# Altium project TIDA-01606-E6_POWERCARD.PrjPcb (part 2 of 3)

## Sheet TIDA-01606-E6_POWERCARD_Power Stage_Pg2.SchDoc
size 431 x 279 mm; Date: Not shown in title block; ApprovedBy: Not shown in title block; CheckedBy: Not shown in title block; Author: Not shown in title block; CompanyName: Not shown in title block; DrawnBy: Murali P; Engineer: Not shown in title block; Organization: Not shown in title block; Address1: Not shown in title block; Address2: Not shown in title block; Address3: Not shown in title block; Address4: Not shown in title block; DocumentNumber: 1; Revision: Use project parameter SCH_Rev; SheetNumber: 2; SheetTotal: 7; PageSetup: Record=PageOptions¦CenterHorizontal=True¦CenterVertical=True¦PrintScale=1.00¦XCorrection=1.00¦YCorrection=1.00¦PrintKind=0¦BorderSize=5000000¦LeftOffset=0¦BottomOffset=0¦Orientation=2¦PaperLength=1000¦PaperWidth=1000¦Scale=100¦PaperSource=15¦PrintQuality=600¦MediaType=1¦DitherType=10¦PaperKind=Letter¦PrintScaleMode=1
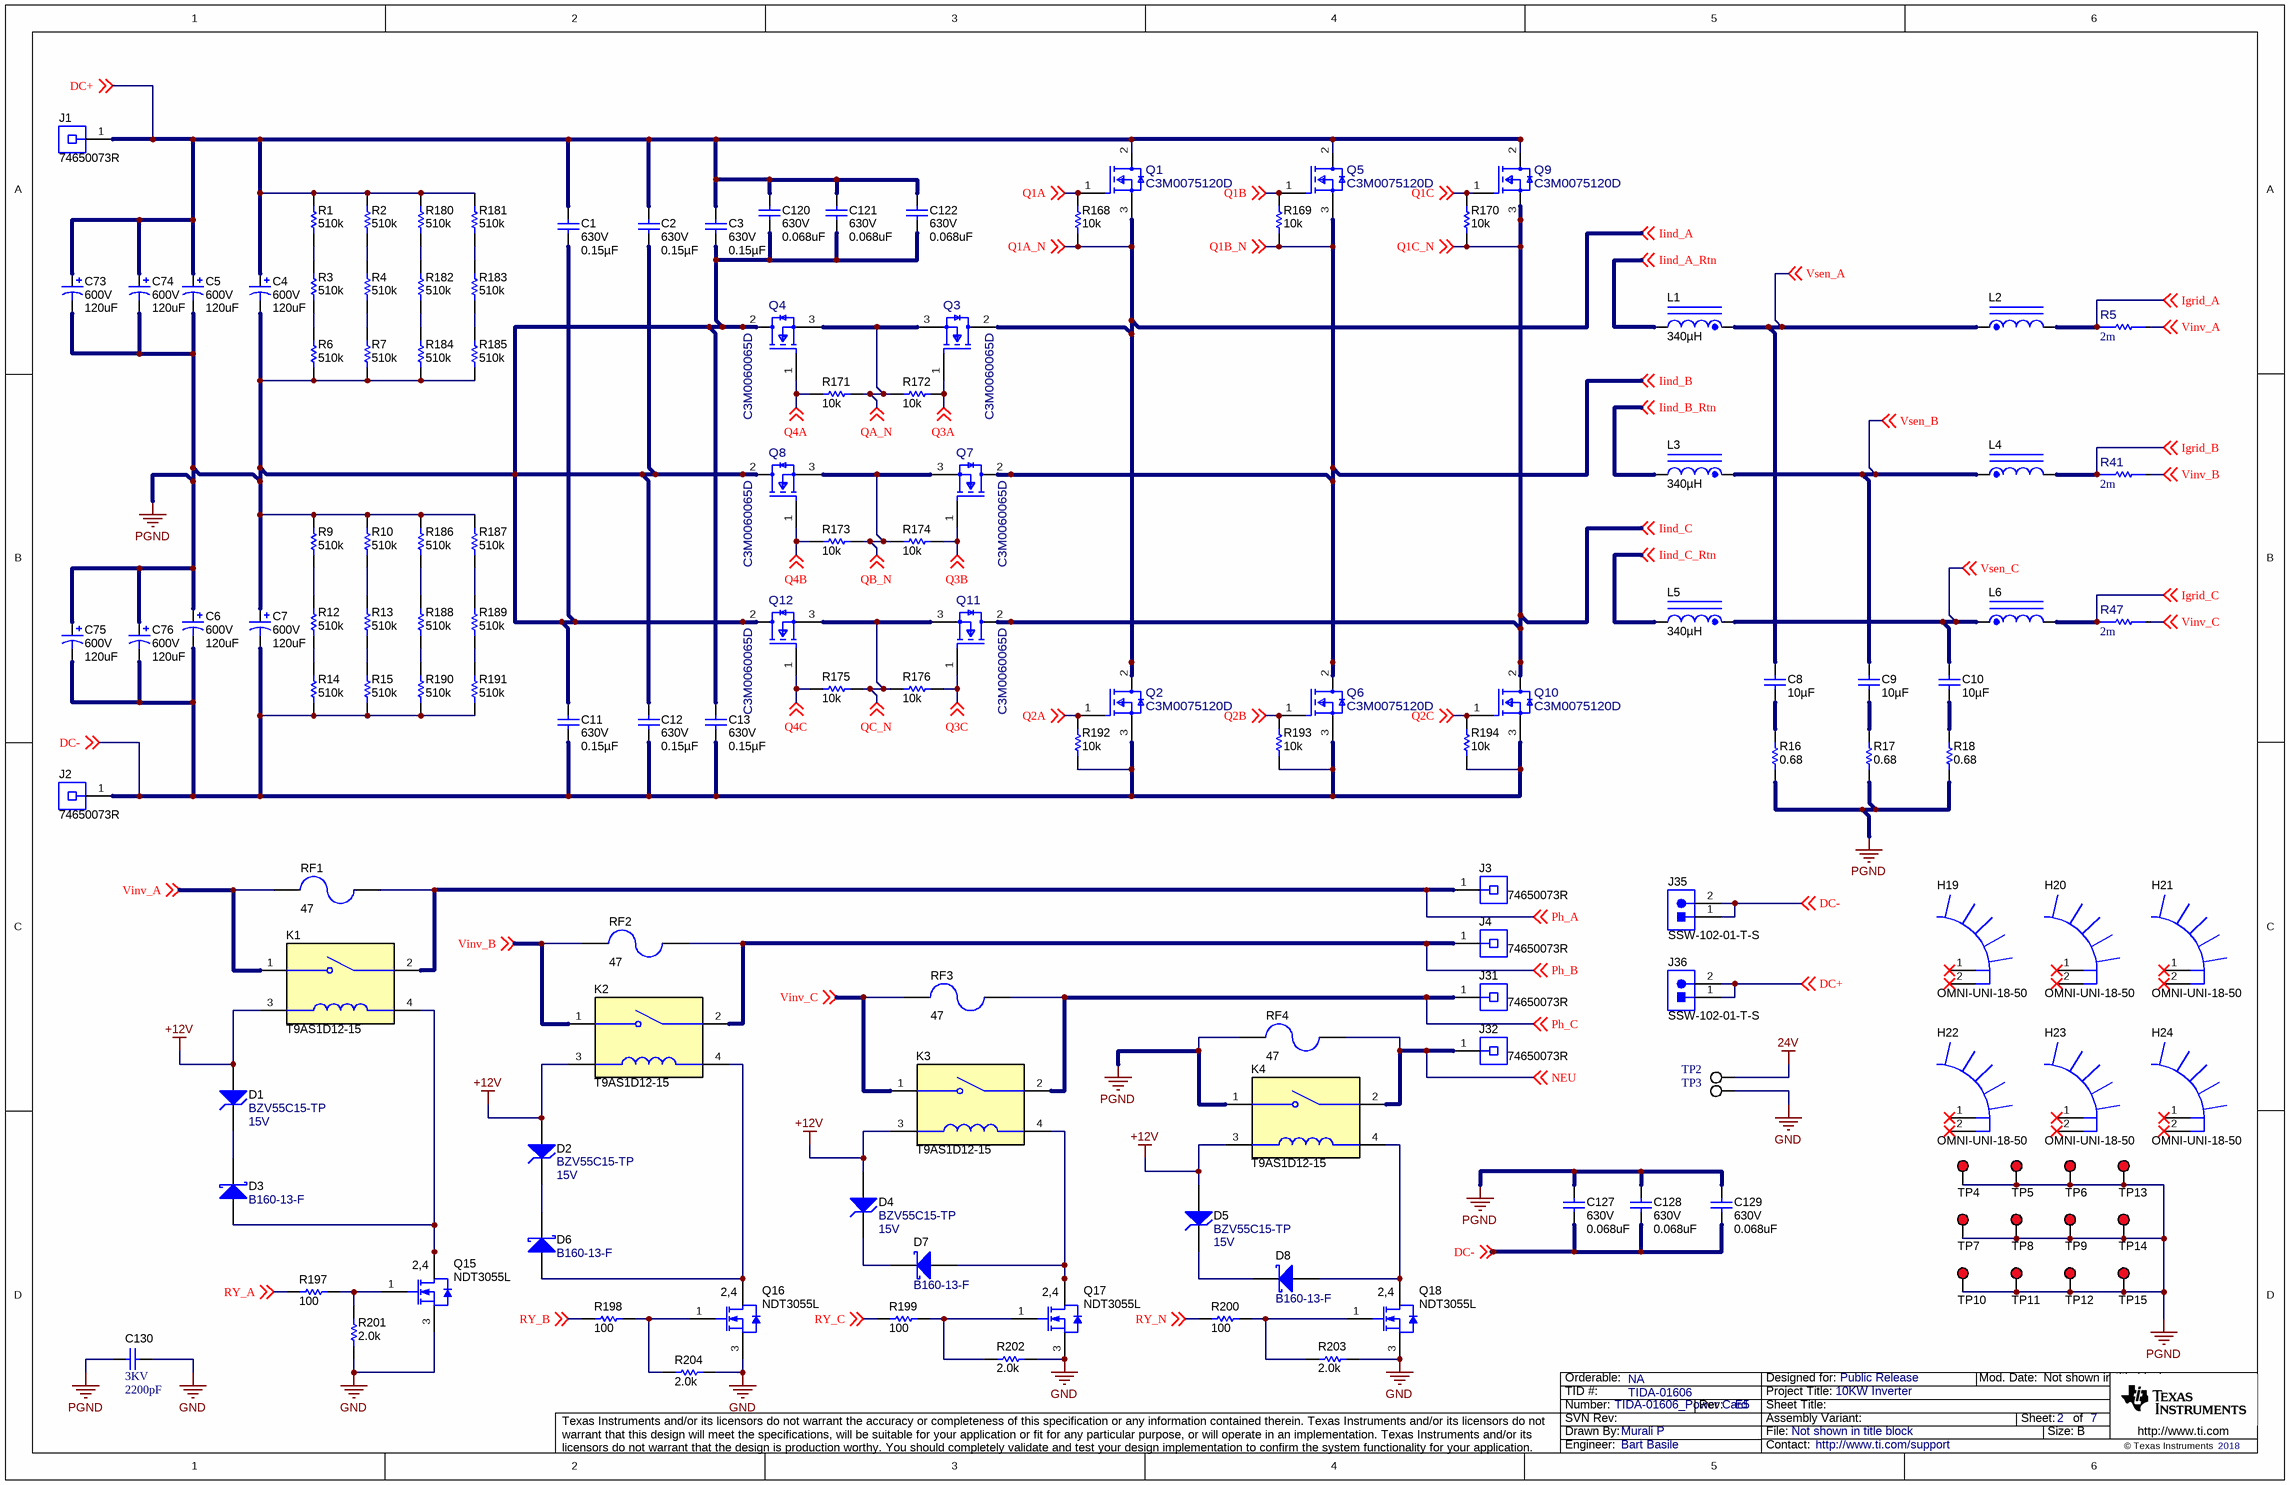
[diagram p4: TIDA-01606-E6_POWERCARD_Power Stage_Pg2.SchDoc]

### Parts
C1  VDC_V: 630V  ValueDisplayed: 0.15µF  [WCAP-FTBP_1800x700x1300]  (hidden comment: 890303325008CS)
C2  VDC_V: 630V  ValueDisplayed: 0.15µF  [WCAP-FTBP_1800x700x1300]  (hidden comment: 890303325008CS)
C3  VDC_V: 630V  ValueDisplayed: 0.15µF  [WCAP-FTBP_1800x700x1300]  (hidden comment: 890303325008CS)
C4  VDC_V: 600V  ValueDisplayed: 120uF  [Nichicon_3000x4500_Snap]  (hidden comment: LGN2X121MELB45)
C5  VDC_V: 600V  ValueDisplayed: 120uF  [Nichicon_3000x4500_Snap]  (hidden comment: LGN2X121MELB45)
C6  VDC_V: 600V  ValueDisplayed: 120uF  [Nichicon_3000x4500_Snap]  (hidden comment: LGN2X121MELB45)
C7  VDC_V: 600V  ValueDisplayed: 120uF  [Nichicon_3000x4500_Snap]  (hidden comment: LGN2X121MELB45)
C8  ValueDisplayed: 10µF  [B32926_42.5mm]  (hidden comment: B32926C3106K000)
C9  ValueDisplayed: 10µF  [B32926_42.5mm]  (hidden comment: B32926C3106K000)
C10  ValueDisplayed: 10µF  [B32926_42.5mm]  (hidden comment: B32926C3106K000)
C11  VDC_V: 630V  ValueDisplayed: 0.15µF  [WCAP-FTBP_1800x700x1300]  (hidden comment: 890303325008CS)
C12  VDC_V: 630V  ValueDisplayed: 0.15µF  [WCAP-FTBP_1800x700x1300]  (hidden comment: 890303325008CS)
C13  VDC_V: 630V  ValueDisplayed: 0.15µF  [WCAP-FTBP_1800x700x1300]  (hidden comment: 890303325008CS)
C73  VDC_V: 600V  ValueDisplayed: 120uF  [Nichicon_3000x4500_Snap]  (hidden comment: LGN2X121MELB45)
C74  VDC_V: 600V  ValueDisplayed: 120uF  [Nichicon_3000x4500_Snap]  (hidden comment: LGN2X121MELB45)
C75  VDC_V: 600V  ValueDisplayed: 120uF  [Nichicon_3000x4500_Snap]  (hidden comment: LGN2X121MELB45)
C76  VDC_V: 600V  ValueDisplayed: 120uF  [Nichicon_3000x4500_Snap]  (hidden comment: LGN2X121MELB45)
C120  VDC_V: 630V  ValueDisplayed: 0.068uF  [B32921_12mm]  (hidden comment: B32921C3683K)
C121  VDC_V: 630V  ValueDisplayed: 0.068uF  [B32921_12mm]  (hidden comment: B32921C3683K)
C122  VDC_V: 630V  ValueDisplayed: 0.068uF  [B32921_12mm]  (hidden comment: B32921C3683K)
C127  VDC_V: 630V  ValueDisplayed: 0.068uF  [B32921_12mm]  (hidden comment: B32921C3683K)
C128  VDC_V: 630V  ValueDisplayed: 0.068uF  [B32921_12mm]  (hidden comment: B32921C3683K)
C129  VDC_V: 630V  ValueDisplayed: 0.068uF  [B32921_12mm]  (hidden comment: B32921C3683K)
C130  VDC_V: 3KV  ValueDisplayed: 2200pF  [CAPRD1000W60D900H1200]  (hidden comment: CK45-B3FD222KYVNA)
D1  BZV55C15-TP  value 15V  [MiniMELF]
D2  BZV55C15-TP  value 15V  [MiniMELF]
D3  B160-13-F  [SMA]
D4  BZV55C15-TP  value 15V  [MiniMELF]
D5  BZV55C15-TP  value 15V  [MiniMELF]
D6  B160-13-F  [SMA]
D7  B160-13-F  [SMA]
D8  B160-13-F  [SMA]
H19  OMNI-UNI-18-50  [HSINK_OMNI-UNI-18-50]
H20  OMNI-UNI-18-50  [HSINK_OMNI-UNI-18-50]
H21  OMNI-UNI-18-50  [HSINK_OMNI-UNI-18-50]
H22  OMNI-UNI-18-50  [HSINK_OMNI-UNI-18-50]
H23  OMNI-UNI-18-50  [HSINK_OMNI-UNI-18-50]
H24  OMNI-UNI-18-50  [HSINK_OMNI-UNI-18-50]
J1  74650073R  [Wurth_WP-THRBU]
J2  74650073R  [Wurth_WP-THRBU]
J3  74650073R  [Wurth_WP-THRBU]
J4  74650073R  [Wurth_WP-THRBU]
J31  74650073R  [Wurth_WP-THRBU]
J32  74650073R  [Wurth_WP-THRBU]
J35  SSW-102-01-T-S  [Samtec_SSW-102-01-x-S]
J36  SSW-102-01-T-S  [Samtec_SSW-102-01-x-S]
K1  T9AS1D12-15  [Relay_T9AS1D12]
K2  T9AS1D12-15  [Relay_T9AS1D12]
K3  T9AS1D12-15  [Relay_T9AS1D12]
K4  T9AS1D12-15  [Relay_T9AS1D12]
L1  ValueDisplayed: 340µH  [750343810]  (hidden comment: 750343810)
L2  750343811  [750343811]  (value not drawn)
L3  ValueDisplayed: 340µH  [750343810]  (hidden comment: 750343810)
L4  750343811  [750343811]  (value not drawn)
L5  ValueDisplayed: 340µH  [750343810]  (hidden comment: 750343810)
L6  750343811  [750343811]  (value not drawn)
Q1  C3M0075120D  [FP-C3M0075120D_TO-247-3-MFG]
Q2  C3M0075120D  [FP-C3M0075120D_TO-247-3-MFG]
Q3  C3M0060065D  [FP-C3M0060065D_TO-247-3-MFG]
Q4  C3M0060065D  [FP-C3M0060065D_TO-247-3-MFG]
Q5  C3M0075120D  [FP-C3M0075120D_TO-247-3-MFG]
Q6  C3M0075120D  [FP-C3M0075120D_TO-247-3-MFG]
Q7  C3M0060065D  [FP-C3M0060065D_TO-247-3-MFG]
Q8  C3M0060065D  [FP-C3M0060065D_TO-247-3-MFG]
Q9  C3M0075120D  [FP-C3M0075120D_TO-247-3-MFG]
Q10  C3M0075120D  [FP-C3M0075120D_TO-247-3-MFG]
Q11  C3M0060065D  [FP-C3M0060065D_TO-247-3-MFG]
Q12  C3M0060065D  [FP-C3M0060065D_TO-247-3-MFG]
Q15  NDT3055L  [SOT-223]
Q16  NDT3055L  [SOT-223]
Q17  NDT3055L  [SOT-223]
Q18  NDT3055L  [SOT-223]
R1  ValueDisplayed: 510k  [2010]  (hidden comment: CRCW2010510KJNEF)
R2  ValueDisplayed: 510k  [2010]  (hidden comment: CRCW2010510KJNEF)
R3  ValueDisplayed: 510k  [2010]  (hidden comment: CRCW2010510KJNEF)
R4  ValueDisplayed: 510k  [2010]  (hidden comment: CRCW2010510KJNEF)
R5  value 2m  [FP-PSR400ITQFJ2L00_3921-MFG]  (hidden comment: PSR400ITQFJ2L00)
R6  ValueDisplayed: 510k  [2010]  (hidden comment: CRCW2010510KJNEF)
R7  ValueDisplayed: 510k  [2010]  (hidden comment: CRCW2010510KJNEF)
R9  ValueDisplayed: 510k  [2010]  (hidden comment: CRCW2010510KJNEF)
R10  ValueDisplayed: 510k  [2010]  (hidden comment: CRCW2010510KJNEF)
R12  ValueDisplayed: 510k  [2010]  (hidden comment: CRCW2010510KJNEF)
R13  ValueDisplayed: 510k  [2010]  (hidden comment: CRCW2010510KJNEF)
R14  ValueDisplayed: 510k  [2010]  (hidden comment: CRCW2010510KJNEF)
R15  ValueDisplayed: 510k  [2010]  (hidden comment: CRCW2010510KJNEF)
R16  value 0.68  [SQM_7]  (hidden comment: SQMW7R68J)
R17  value 0.68  [SQM_7]  (hidden comment: SQMW7R68J)
R18  value 0.68  [SQM_7]  (hidden comment: SQMW7R68J)
R41  value 2m  [FP-PSR400ITQFJ2L00_3921-MFG]  (hidden comment: PSR400ITQFJ2L00)
R47  value 2m  [FP-PSR400ITQFJ2L00_3921-MFG]  (hidden comment: PSR400ITQFJ2L00)
R168  ValueDisplayed: 10k  [1206]  (hidden comment: CRCW120610K0JNEA)
R169  ValueDisplayed: 10k  [1206]  (hidden comment: CRCW120610K0JNEA)
R170  ValueDisplayed: 10k  [1206]  (hidden comment: CRCW120610K0JNEA)
R171  ValueDisplayed: 10k  [1206]  (hidden comment: CRCW120610K0JNEA)
R172  ValueDisplayed: 10k  [1206]  (hidden comment: CRCW120610K0JNEA)
R173  ValueDisplayed: 10k  [1206]  (hidden comment: CRCW120610K0JNEA)
R174  ValueDisplayed: 10k  [1206]  (hidden comment: CRCW120610K0JNEA)
R175  ValueDisplayed: 10k  [1206]  (hidden comment: CRCW120610K0JNEA)
R176  ValueDisplayed: 10k  [1206]  (hidden comment: CRCW120610K0JNEA)
R180  ValueDisplayed: 510k  [2010]  (hidden comment: CRCW2010510KJNEF)
R181  ValueDisplayed: 510k  [2010]  (hidden comment: CRCW2010510KJNEF)
R182  ValueDisplayed: 510k  [2010]  (hidden comment: CRCW2010510KJNEF)
R183  ValueDisplayed: 510k  [2010]  (hidden comment: CRCW2010510KJNEF)
R184  ValueDisplayed: 510k  [2010]  (hidden comment: CRCW2010510KJNEF)
R185  ValueDisplayed: 510k  [2010]  (hidden comment: CRCW2010510KJNEF)
R186  ValueDisplayed: 510k  [2010]  (hidden comment: CRCW2010510KJNEF)
R187  ValueDisplayed: 510k  [2010]  (hidden comment: CRCW2010510KJNEF)
R188  ValueDisplayed: 510k  [2010]  (hidden comment: CRCW2010510KJNEF)
R189  ValueDisplayed: 510k  [2010]  (hidden comment: CRCW2010510KJNEF)
R190  ValueDisplayed: 510k  [2010]  (hidden comment: CRCW2010510KJNEF)
R191  ValueDisplayed: 510k  [2010]  (hidden comment: CRCW2010510KJNEF)
R192  ValueDisplayed: 10k  [1206]  (hidden comment: CRCW120610K0JNEA)
R193  ValueDisplayed: 10k  [1206]  (hidden comment: CRCW120610K0JNEA)
R194  ValueDisplayed: 10k  [1206]  (hidden comment: CRCW120610K0JNEA)
R197  ValueDisplayed: 100  [0603]  (hidden comment: ESR03EZPJ101)
R198  ValueDisplayed: 100  [0603]  (hidden comment: ESR03EZPJ101)
R199  ValueDisplayed: 100  [0603]  (hidden comment: ESR03EZPJ101)
R200  ValueDisplayed: 100  [0603]  (hidden comment: ESR03EZPJ101)
R201  ValueDisplayed: 2.0k  [0603]  (hidden comment: CRCW06032K00JNEA)
R202  ValueDisplayed: 2.0k  [0603]  (hidden comment: CRCW06032K00JNEA)
R203  ValueDisplayed: 2.0k  [0603]  (hidden comment: CRCW06032K00JNEA)
R204  ValueDisplayed: 2.0k  [0603]  (hidden comment: CRCW06032K00JNEA)
RF1  ValueDisplayed: 47  [EMC2]  (hidden comment: EMC2-47RKI)
RF2  ValueDisplayed: 47  [EMC2]  (hidden comment: EMC2-47RKI)
RF3  ValueDisplayed: 47  [EMC2]  (hidden comment: EMC2-47RKI)
RF4  ValueDisplayed: 47  [EMC2]  (hidden comment: EMC2-47RKI)
TP2  5002  [Keystone5002]  (value not drawn)
TP3  5002  [Keystone5002]  (value not drawn)
TP4  5000  [Keystone5000]  (value not drawn)
TP5  5000  [Keystone5000]  (value not drawn)
TP6  5000  [Keystone5000]  (value not drawn)
TP7  5000  [Keystone5000]  (value not drawn)
TP8  5000  [Keystone5000]  (value not drawn)
TP9  5000  [Keystone5000]  (value not drawn)
TP10  5000  [Keystone5000]  (value not drawn)
TP11  5000  [Keystone5000]  (value not drawn)
TP12  5000  [Keystone5000]  (value not drawn)
TP13  5000  [Keystone5000]  (value not drawn)
TP14  5000  [Keystone5000]  (value not drawn)
TP15  5000  [Keystone5000]  (value not drawn)

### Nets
24V: TP2.1
+12V: D1.2(A) D2.2(A) D4.2(A) D5.2(A) K1.3 K2.3 K3.3 K4.3
GND: C130.1 Q15.3(S) Q16.3(S) Q17.3(S) Q18.3(S) R201.1 R202.1 R203.1 R204.1 TP3.1
PGND: C1.2 C2.2 C3.2 C4.2(-) C5.2(-) C6.1(+) C7.1(+) C11.1 C12.1 C13.1 C73.2(-) C74.2(-) C75.1(+) C76.1(+) C120.2 C121.2 C122.2 C127.1 C128.1 C129.1 C130.2 K4.1 Q4.2(Drain) Q8.2(Drain) Q12.2(Drain) R6.1 R7.1 R9.2 R10.2 R16.1 R17.1 R18.1 R184.1 R185.1 R186.2 R187.2 RF4.2 TP4.1 TP5.1 TP6.1 TP7.1 TP8.1 TP9.1 TP10.1 TP11.1 TP12.1 TP13.1 TP14.1 TP15.1
Vinv_A: K1.1 R5.2 RF1.2 ; off-sheet Vinv_A  [project net GND_AMC1]
Vinv_B: K2.1 R41.2 RF2.2 ; off-sheet Vinv_B  [project net GND_AMC2]
Vinv_C: K3.1 R47.2 RF3.2 ; off-sheet Vinv_C  [project net GND_AMC3]
DC+: C1.1 C2.1 C3.1 C4.1(+) C5.1(+) C73.1(+) C74.1(+) C120.1 C121.1 C122.1 J1.1 J36.1 J36.2 Q1.2(D) Q5.2(D) Q9.2(D) R1.2 R2.2 R180.2 R181.2 ; off-sheet DC+
DC-: C6.2(-) C7.2(-) C11.2 C12.2 C13.2 C75.2(-) C76.2(-) C127.2 C128.2 C129.2 J2.1 J35.1 J35.2 Q2.3(S) Q6.3(S) Q10.3(S) R14.1 R15.1 R190.1 R191.1 R192.1 R193.1 R194.1 ; off-sheet DC-
Igrid_A: L2.2 R5.1 ; off-sheet Igrid_A
Igrid_B: L4.2 R41.1 ; off-sheet Igrid_B
Igrid_C: L6.2 R47.1 ; off-sheet Igrid_C
Iind_A: Q1.3(S) Q2.2(D) Q3.2(Drain) R168.1 ; off-sheet Iind_A, off-sheet Q1A_N  [also labelled Q1A_N]
Iind_A_Rtn: L1.2 ; off-sheet Iind_A_Rtn
Iind_B: Q5.3(S) Q6.2(D) Q7.2(Drain) R169.1 ; off-sheet Iind_B, off-sheet Q1B_N  [also labelled Q1B_N]
Iind_B_Rtn: L3.2 ; off-sheet Iind_B_Rtn
Iind_C: Q9.3(S) Q10.2(D) Q11.2(Drain) R170.1 ; off-sheet Iind_C, off-sheet Q1C_N  [also labelled Q1C_N]
Iind_C_Rtn: L5.2 ; off-sheet Iind_C_Rtn
NEU: J32.1 K4.2 RF4.1 ; off-sheet NEU
Ph_A: J3.1 K1.2 RF1.1 ; off-sheet Ph_A
Ph_B: J4.1 K2.2 RF2.1 ; off-sheet Ph_B
Ph_C: J31.1 K3.2 RF3.1 ; off-sheet Ph_C
Q1A: Q1.1(G) R168.2 ; off-sheet Q1A
Q1B: Q5.1(G) R169.2 ; off-sheet Q1B
Q1C: Q9.1(G) R170.2 ; off-sheet Q1C
Q2A: Q2.1(G) R192.2 ; off-sheet Q2A
Q2B: Q6.1(G) R193.2 ; off-sheet Q2B
Q2C: Q10.1(G) R194.2 ; off-sheet Q2C
Q3A: Q3.1(Gate) R172.1 ; off-sheet Q3A
Q3B: Q7.1(Gate) R174.1 ; off-sheet Q3B
Q3C: Q11.1(Gate) R176.1 ; off-sheet Q3C
Q4A: Q4.1(Gate) R171.2 ; off-sheet Q4A
Q4B: Q8.1(Gate) R173.2 ; off-sheet Q4B
Q4C: Q12.1(Gate) R175.2 ; off-sheet Q4C
QA_N: Q3.3(Source) Q4.3(Source) R171.1 R172.2 ; off-sheet QA_N
QB_N: Q7.3(Source) Q8.3(Source) R173.1 R174.2 ; off-sheet QB_N
QC_N: Q11.3(Source) Q12.3(Source) R175.1 R176.2 ; off-sheet QC_N
RY_A: R197.1 ; off-sheet RY_A
RY_B: R198.1 ; off-sheet RY_B
RY_C: R199.1 ; off-sheet RY_C
RY_N: R200.1 ; off-sheet RY_N
Vsen_A: C8.1 L1.1 L2.1 ; off-sheet Vsen_A
Vsen_B: C9.1 L3.1 L4.1 ; off-sheet Vsen_B
Vsen_C: C10.1 L5.1 L6.1 ; off-sheet Vsen_C
NetC8_2: C8.2 R16.2
NetC9_2: C9.2 R17.2
NetC10_2: C10.2 R18.2
NetD1_1: D1.1(K) D3.1(K)
NetD2_1: D2.1(K) D6.1(K)
NetD3_2: D3.2(A) K1.4 Q15.2(D) Q15.4(D)
NetD4_1: D4.1(K) D7.1(K)
NetD5_1: D5.1(K) D8.1(K)
NetD6_2: D6.2(A) K2.4 Q16.2(D) Q16.4(D)
NetD7_2: D7.2(A) K3.4 Q17.2(D) Q17.4(D)
NetD8_2: D8.2(A) K4.4 Q18.2(D) Q18.4(D)
NetQ15_1: Q15.1(G) R197.2 R201.2
NetQ16_1: Q16.1(G) R198.2 R204.2
NetQ17_1: Q17.1(G) R199.2 R202.2
NetQ18_1: Q18.1(G) R200.2 R203.2
NetR1_1: R1.1 R3.2
NetR2_1: R2.1 R4.2
NetR3_1: R3.1 R6.2
NetR4_1: R4.1 R7.2
NetR9_1: R9.1 R12.2
NetR10_1: R10.1 R13.2
NetR12_1: R12.1 R14.2
NetR13_1: R13.1 R15.2
NetR180_1: R180.1 R182.2
NetR181_1: R181.1 R183.2
NetR182_1: R182.1 R184.2
NetR183_1: R183.1 R185.2
NetR186_1: R186.1 R188.2
NetR187_1: R187.1 R189.2
NetR188_1: R188.1 R190.2
NetR189_1: R189.1 R191.2

Not connected (* = marked no-connect by the designer): H19 1* 2*; H20 1* 2*; H21 1* 2*; H22 1* 2*; H23 1* 2*; H24 1* 2*

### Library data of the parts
C1-C3 C11-C13 = CMP-0081646-1: CAP, Film, 0.15 µF, 630 V,+/- 5%, 0.06122 ohm, TH; Manufacturer: Wurth Elektronik; Cap_F: 150nF; SizeAreaWB_mm2: 180; SizeArea_mm2: 126; AEC Qualified: N; AEC Category: Q200; Value: 0.15uF; TaMax_C: 105°C; SizeZ_mm: 14; TaMin_C: -40°C; SizeY_mm: 7; SizeX_mm: 18; Cap_Case: 18x7x13mm
C4-C7 C73-C76 = CMP-0010058-3: CAP, AL, 120 uF, 600 V, +/- 20%, TH; Manufacturer: Nichicon; TaMin_C: -25°C; Polarized: Y; SizeAreaWB_mm2: 1024; Value1: Unknown; U/M: EA; Value: 120uF; TaMax_C: 105°C; SizeZ_mm: 47; SizeX_mm: 30; Cap_Case: 30x45mm; SizeArea_mm2: 900; CompType: Capacitor; AEC Qualified: N; Cap_F: 120µF; IRMS_A: 7.4dA; AEC Category: Q200
C8-C10 = CMP-0083863-1: CAP, Film, 10 µF,  V,+/- 10%, AEC-Q200 Grade 1, TH; Manufacturer: TDK; Polarized: N; Value: 10uF; TaMin_C: -40°C; TaMax_C: 110°C; Cap_Case: 41.5x28mm; SizeAreaWB_mm2: 1305; SizeArea_mm2: 1162; SizeX_mm: 41.5; SizeY_mm: 28; SizeZ_mm: 42.5; AEC Category: Q200; AEC Qualified: Y; AEC Grade: 1
C120-C122 C127-C129 = CMP-0012400-3: CAP, Film, 0.068 uF, 630 V, +/- 10%, TH; Manufacturer: TDK; Polarized: N; SizeAreaWB_mm2: 120; Value1: Unknown; TaMax_C: 110°C; SizeZ_mm: 12; SizeX_mm: 6; SizeY_mm: 13; SizeArea_mm2: 78; Cap_F: 68nF; AEC Category: Q200
C130 = CMP-0009601-2: CAP, CERM, 2200 pF, 3KV, +/- 20%, E, Cap, 7x12x9 mm; Manufacturer: MuRata; TaMin_C: -25°C; Polarized: N; SizeAreaWB_mm2: 121.5; Value1: Unknown; U/M: EA; Value: 2200pF; TaMax_C: 85°C; SizeZ_mm: 12.5; SizeX_mm: 11.5; SizeY_mm: 7; Value2: 250V; SizeArea_mm2: 80.5; CompType: Capacitor; Cap_F: 2.2nF; AEC Category: Q200
D1 D2 D4 D5 = CMP-0006039-4: Diode, Zener, 15 V, 500 mW, MiniMELF; Manufacturer: Micro Commercial Components; Power_W: 500mW; Value1: 0.5W; RJA_CperW: 500; SizeAreaWB_mm2: 11.025; SizeArea_mm2: 5.075; SizeX_mm: 3.5; SizeY_mm: 1.45; SizeZ_mm: 1.5; AEC Category: Q101; AEC Qualified: N
D3 D6-D8 = CMP-0028389-2: Diode, Schottky, 60 V, 1 A, SMA; Manufacturer: Diodes Inc.; Vf_V: 700mV; Value: 60V; Value1: 1A; Value2: 0.7V; TJmax_C: 150°C; RJC_CperW: 20; SizeAreaWB_mm2: 37.3428; SizeArea_mm2: 16.3228; SizeX_mm: 5.59; SizeY_mm: 2.92; SizeZ_mm: 2.87; AEC Category: Q101; Green_Lifecycle: Not Set; Green_REACh: Incomplete
H19-H24 = CMP-0079407-1: Heat Sink, TO-247, TO-264, Vertical; Manufacturer: Wakefield-Vette
J1-J4 J31 J32 = CMP-0078526-1: Power Element Bush, M3, TH; Manufacturer: Wurth Elektronik; Gender: Female; Current_A: 50A; ContactFinish: Tin; CompType: Screw Terminal
J35 J36 = CMP-0075620-1: Receptacle, 2x1, 2.54mm, Tin, TH; Manufacturer: Samtec; Pitch_mm: 2.54; Gender: Female; Cert_CSA: Y; Current_A: 5.7A; CT: False; Row_Count: 1
K1-K4 = CMP-0078608-2: Relay, SPST-NO (1 Form A), 30 A, 15 V, TH; Manufacturer: TE Connectivity; Contact Rating_A: 30A; Turn On Voltage (Max)_VDC: 11.25V; Coil Power_W: 1W; Coil Resistance_ohm: 225; SizeAreaWB_mm2: 1015.6293; Time Operate (s): 15ms; Coil Current_A: 66.7mA; SizeZ_mm: 20.4; SizeX_mm: 32.51; SizeY_mm: 27.43; SizeArea_mm2: 891.7493; Turn Off Voltage (Min)_VDC: 1.5V; Coil Type: Non Latching; Coil Voltage_VDC: 15V
L1 L3 L5 = CMP-0082074-1: Inductor, Toroid, 340 µH, 15 A, 0.05 ohm, TH; Manufacturer: Wurth Elektronik; SizeAreaWB_mm2: 4629.4416; Irms: 15A @ C rise; SizeArea_mm2: 4361.2816; AEC Qualified: N; AEC Category: Q200; Value: 340uH; SizeZ_mm: 39.88; Imax_A: 15A; SizeY_mm: 66.04; Isat: 24A @ % inductance drop; DCR_ohm: 0.05
L2 L4 L6 = CMP-0082075-1: Inductor, Toroid, 15 A, 0.006 ohm, TH; Manufacturer: Wurth Elektronik; SizeAreaWB_mm2: 1188; SizeArea_mm2: 1050; Irms: 15A @ C rise; AEC Qualified: N; AEC Category: Q200; SizeZ_mm: 42; Imax_A: 15A; Isat: 15A @ % inductance drop; DCR_ohm: 6m; SizeX_mm: 25
Q1 Q2 Q5 Q6 Q9 Q10 = CMP-0097459-1: N-Channel 1200 V 30A (Tc) 113.6W (Tc) Through Hole TO-247-3; Manufacturer: Wolfspeed; Rdson45_ohm: 75m; Drain To Source Breakdown Voltage: 1200V; Reverse Recovery Charge: 279nC; Power_W: 136W; Threshold Vgs Min: 1.8V; IdsMax_A: 32A; SizeZ_mm: 25.5mm; Pulse Drain Current: 80A; Standoff Height: 4.1mm; Turn On Delay Time: 56ns; VdsMax_V: 1.2kV; Transconductance: 12S; Typ Forward Diode Voltage: 4.5V; TJmax_C: +175°C; Vgs_V: 19V; QgTyp_nC: 54nC @ 15V; AEC Qualified: No; Rthja Max: 40°C/W; Turn Off Delay Time: 32ns; Number Of Channels: 1; Reverse Recovery Time: 48ns; Input Capacitace At Vds: 1390pF @ 1000V; Threshold Vgs Max: 3.6V; ChMode: False
Q3 Q4 Q7 Q8 Q11 Q12 = CMP-0097458-1: N-Channel 650 V 37A (Tc) 150W (Tc) Through Hole TO-247-3; Manufacturer: Wolfspeed; Reverse Recovery Time: 20ns; Transconductance: 10S; Number Of N Channels: 1; Threshold Vgs Min: 1.8V; Typ Forward Diode Voltage: 5.1V; AEC Qualified: No; IdsMax_A: 29A; TJmax_C: +175°C; Standoff Height: 4.1mm; Pulse Drain Current: 99A; VdsMax_V: 650V; ChMode: False; Reverse Recovery Charge: 190nC; SizeZ_mm: 25.5mm; Turn Off Delay Time: 17ns; Rthja Max: 40°C/W; QgTyp_nC: 46nC @ 15V; Vgs_V: 19V; Threshold Vgs Max: 3.6V; Input Capacitace At Vds: 1020pF @ 600V; Rdson45_ohm: 60m; Turn On Delay Time: 9ns
Q15-Q18 = CMP-0081320-1: MOSFET, N-CH, 60 V, 4 A, SOT-223; Manufacturer: ON Semiconductor; Alternate Manufacturer: None; ChType: N; Value: 60V; Value1: 0.12 ohm; Rdson45_ohm: 1.2d; Value2: 13 nC; QgTyp_nC: 13; Vgs_V: 20V; IdsMax_A: 4A; SizeAreaWB_mm2: 76.5; SizeArea_mm2: 45.5; SizeX_mm: 6.5; SizeY_mm: 7; SizeZ_mm: 1.6; AEC Category: Q101
R1-R4 R6 R7 R9 R10 R12-R15 R180-R191 = CMP-0016151-3: RES, 510 k, 5%, 0.75 W, AEC-Q200 Grade 0, 2010; Manufacturer: Vishay-Dale; Value: 510k; Power_W: 750mW; Value2: 0.75W; VDC_V: 400V; TempCo: 200 ppm/C; SizeArea_mm2: 12.5; SizeX_mm: 5; SizeY_mm: 2.5; SizeZ_mm: 1.66; EIA_Code: E24; AEC Category: Q200; AEC Qualified: Y; AEC Grade: 0
R5 R41 R47 = CMP-0097460-1: 2 mOhms ±1% 4W Chip Resistor Nonstandard Automotive AEC-Q200, Current Sense Metal Element; Manufacturer: Rohm; AEC Qualified: Yes; TempCo: 0/+75ppm/°C; AEC Grade: Grade 0; SizeZ_mm: 1.25mm; Standoff Height: 0.35mm; Power_W: 6W
R16-R18 = CMP-0078524-1: RES, 0.68, 5%, 7 W, 13x9mm; Manufacturer: TE Connectivity; Value_Code: R680; SizeArea_mm2: 117; AEC Qualified: N; AEC Category: Q200; Res_ohm: 6.8d; SizeZ_mm: 40; TempCo: 300 ppm/C; SizeY_mm: 9; Power_W: 7W; SizeX_mm: 13
R168-R176 R192-R194 = CMP-0018576-3: RES, 10 k, 5%, 0.25 W, AEC-Q200 Grade 0, 1206; Manufacturer: Vishay-Dale; Value: 10k; Value_Code: 10k0; Power_W: 250mW; Value2: 0.25W; VDC_V: 200V; TempCo: 200 ppm/C; SizeArea_mm2: 5.12; SizeX_mm: 3.2; SizeY_mm: 1.6; SizeZ_mm: 1.35; EIA_Code: E24; AEC Category: Q200; AEC Qualified: Y; AEC Grade: 0
R197-R200 = CMP-0025882-3: RES, 100, 5%, 0.25 W, AEC-Q200 Grade 0, 0603; Manufacturer: Rohm; Value: 100; Value_Code: 100R; Power_W: 250mW; Value2: 0.25W; VDC_V: 150V; TempCo: 200 ppm/C; SizeArea_mm2: 1.28; SizeX_mm: 1.6; SizeY_mm: 0.8; SizeZ_mm: 1; EIA_Code: E24; AEC Category: Q200; AEC Qualified: Y; AEC Grade: 0; U/M: EA
R201-R204 = CMP-0025768-4: RES, 2.0 k, 5%, 0.1 W, AEC-Q200 Grade 0, 0603; Manufacturer: Vishay-Dale; Value: 2.0k; Res_ohm: 2k; Value_Code: 2k00; Power_W: 100mW; Value2: 0.1W; VDC_V: 75V; TempCo: 200 ppm/C; SizeArea_mm2: 1.28; SizeX_mm: 1.6; SizeY_mm: 0.8; SizeZ_mm: 1; EIA_Code: E24; AEC Category: Q200; AEC Qualified: Y; AEC Grade: 0
RF1-RF4 = CMP-0014288-1: RES, 47, 10%, 2 W, Axial resistor; Manufacturer: TT Electronics/IRC; Power_W: 2W; TempCo: 100 ppm/C; Value_Code: 47R0; U/M: EA; Value: 47; CompType: Fusible Resistor; AEC Category: Q200
TP2 TP3 = CMP-0055139-1: Test Point, Miniature, White, TH; Manufacturer: Keystone; ContactFinish: Silver; Green_Lifecycle: Active; Green_REACh: Passed; CNHeader: FALSE; CT: TRUE
TP4-TP15 = CMP-0055137-1: Test Point, Miniature, Red, TH; Manufacturer: Keystone; CNHeader: FALSE; ContactFinish: Silver; CT: TRUE; Green_Lifecycle: Active; Green_REACh: Passed

## Sheet TIDA-01606-E6_POWERCARD_Power Supply and Protection_Pg3.SchDoc
size 431 x 279 mm; Date: Not shown in title block; ApprovedBy: Not shown in title block; CheckedBy: Not shown in title block; Author: Not shown in title block; CompanyName: Not shown in title block; DrawnBy: Murali P; Engineer: Not shown in title block; Organization: Not shown in title block; Address1: Not shown in title block; Address2: Not shown in title block; Address3: Not shown in title block; Address4: Not shown in title block; DocumentNumber: 1; Revision: Use project parameter SCH_Rev; SheetNumber: 5; SheetTotal: 7; PageSetup: Record=PageOptions¦CenterHorizontal=True¦CenterVertical=True¦PrintScale=1.00¦XCorrection=1.00¦YCorrection=1.00¦PrintKind=0¦BorderSize=5000000¦LeftOffset=0¦BottomOffset=0¦Orientation=2¦PaperLength=1000¦PaperWidth=1000¦Scale=100¦PaperSource=15¦PrintQuality=600¦MediaType=1¦DitherType=10¦PaperKind=Letter¦PrintScaleMode=1
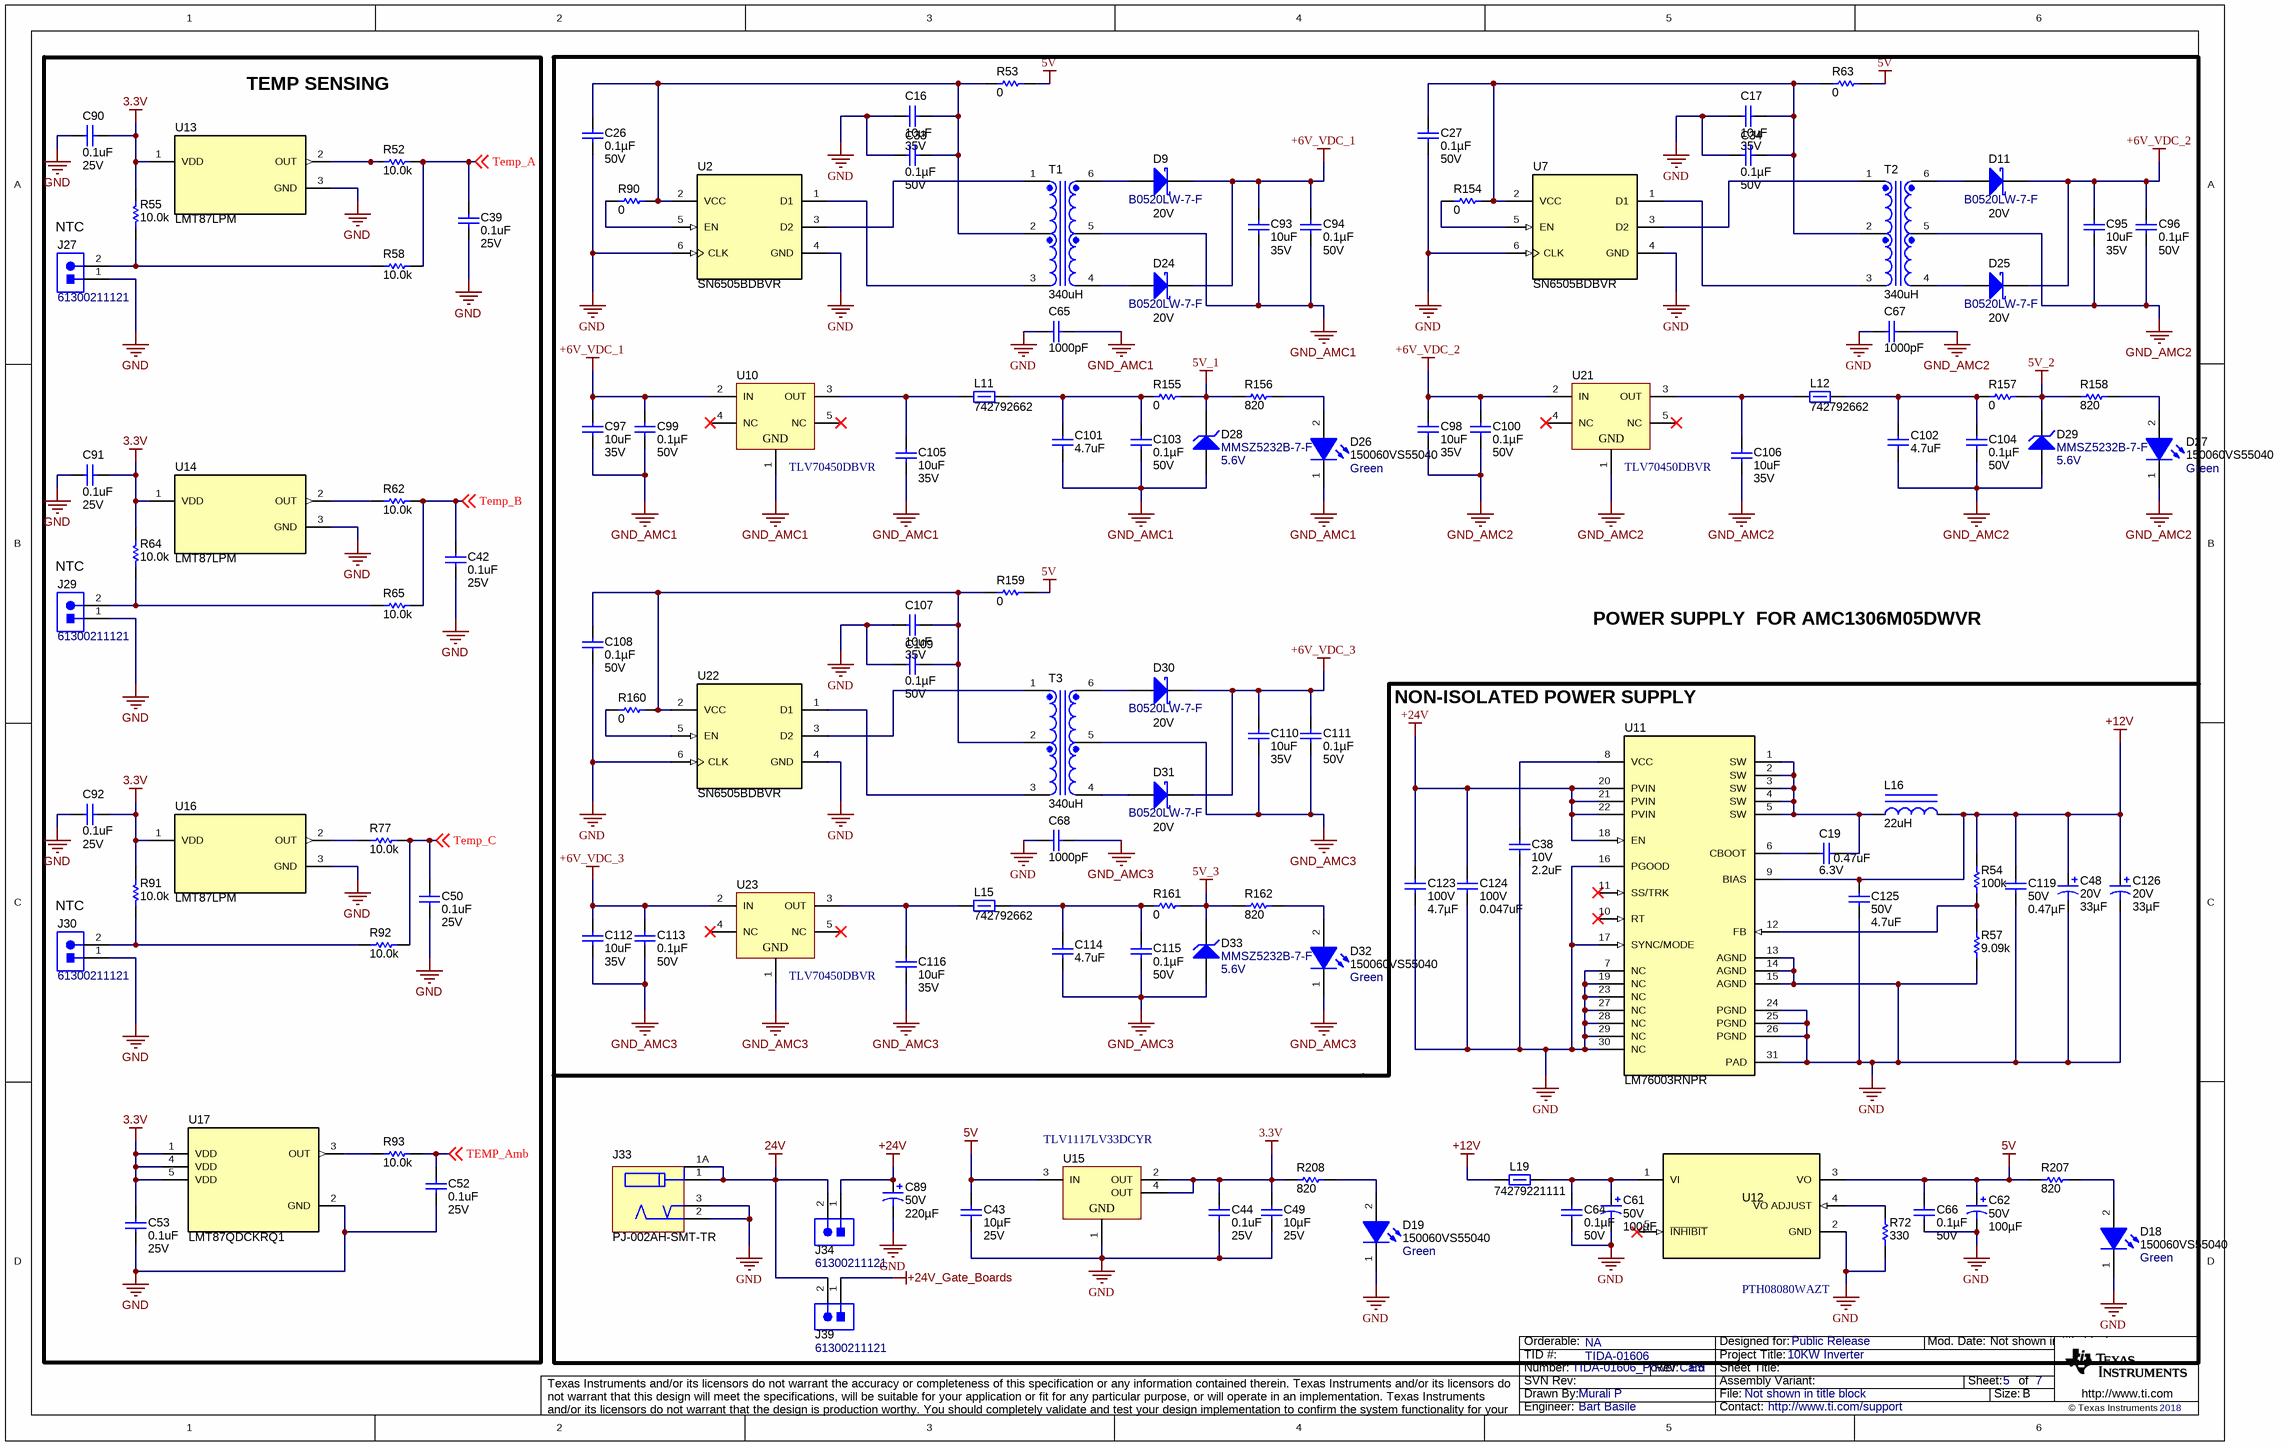
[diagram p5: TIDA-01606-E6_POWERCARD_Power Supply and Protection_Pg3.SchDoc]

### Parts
C16  ValueDisplayed: 10uF  VDC_V: 35V  [1210_270]  (hidden comment: GRM32ER7YA106KA12L)
C17  ValueDisplayed: 10uF  VDC_V: 35V  [1210_270]  (hidden comment: GRM32ER7YA106KA12L)
C19  VDC_V: 6.3V  ValueDisplayed: 0.47uF  [0402]  (hidden comment: GRM155R60J474KE19D)
C26  ValueDisplayed: 0.1µF  VDC_V: 50V  [0603]  (hidden comment: C0603C104K5RACAUTO)
C27  ValueDisplayed: 0.1µF  VDC_V: 50V  [0603]  (hidden comment: C0603C104K5RACAUTO)
C33  ValueDisplayed: 0.1µF  VDC_V: 50V  [0603]  (hidden comment: C0603C104K5RACAUTO)
C34  ValueDisplayed: 0.1µF  VDC_V: 50V  [0603]  (hidden comment: C0603C104K5RACAUTO)
C38  VDC_V: 10V  ValueDisplayed: 2.2uF  [0805_HV]  (hidden comment: GRM216R61A225KE24D)
C39  ValueDisplayed: 0.1uF  VDC_V: 25V  [0603]  (hidden comment: C0603X104K3RACTU)
C42  ValueDisplayed: 0.1uF  VDC_V: 25V  [0603]  (hidden comment: C0603X104K3RACTU)
C43  ValueDisplayed: 10µF  VDC_V: 25V  [1206_180]  (hidden comment: C3216X7R1E106K160AB)
C44  ValueDisplayed: 0.1uF  VDC_V: 25V  [0603]  (hidden comment: C0603X104K3RACTU)
C48  VDC_V: 20V  ValueDisplayed: 33µF  [WCAP-PSLP_630x580]  (hidden comment: 875105444004)
C49  ValueDisplayed: 10µF  VDC_V: 25V  [1206_180]  (hidden comment: C3216X7R1E106K160AB)
C50  ValueDisplayed: 0.1uF  VDC_V: 25V  [0603]  (hidden comment: C0603X104K3RACTU)
C52  ValueDisplayed: 0.1uF  VDC_V: 25V  [0603]  (hidden comment: C0603X104K3RACTU)
C53  ValueDisplayed: 0.1uF  VDC_V: 25V  [0603]  (hidden comment: C0603X104K3RACTU)
C61  VDC_V: 50V  ValueDisplayed: 100µF  [WCAP-ASLL_800x1050]  (hidden comment: 865060653010)
C62  VDC_V: 50V  ValueDisplayed: 100µF  [WCAP-ASLL_800x1050]  (hidden comment: 865060653010)
C64  ValueDisplayed: 0.1µF  VDC_V: 50V  [0603]  (hidden comment: C0603C104K5RACAUTO)
C65  ValueDisplayed: 1000pF  [VY1_900x500x1300]  (hidden comment: VY1102M35Y5UQ63V0)
C66  ValueDisplayed: 0.1µF  VDC_V: 50V  [0603]  (hidden comment: C0603C104K5RACAUTO)
C67  ValueDisplayed: 1000pF  [VY1_900x500x1300]  (hidden comment: VY1102M35Y5UQ63V0)
C68  ValueDisplayed: 1000pF  [VY1_900x500x1300]  (hidden comment: VY1102M35Y5UQ63V0)
C89  VDC_V: 50V  ValueDisplayed: 220µF  [WCAP-ATLI_1000x1600]  (hidden comment: 860080675015)
C90  ValueDisplayed: 0.1uF  VDC_V: 25V  [0603]  (hidden comment: C0603X104K3RACTU)
C91  ValueDisplayed: 0.1uF  VDC_V: 25V  [0603]  (hidden comment: C0603X104K3RACTU)
C92  ValueDisplayed: 0.1uF  VDC_V: 25V  [0603]  (hidden comment: C0603X104K3RACTU)
C93  ValueDisplayed: 10uF  VDC_V: 35V  [1210_270]  (hidden comment: GRM32ER7YA106KA12L)
C94  ValueDisplayed: 0.1µF  VDC_V: 50V  [0603]  (hidden comment: C0603C104K5RACAUTO)
C95  ValueDisplayed: 10uF  VDC_V: 35V  [1210_270]  (hidden comment: GRM32ER7YA106KA12L)
C96  ValueDisplayed: 0.1µF  VDC_V: 50V  [0603]  (hidden comment: C0603C104K5RACAUTO)
C97  ValueDisplayed: 10uF  VDC_V: 35V  [1210_270]  (hidden comment: GRM32ER7YA106KA12L)
C98  ValueDisplayed: 10uF  VDC_V: 35V  [1210_270]  (hidden comment: GRM32ER7YA106KA12L)
C99  ValueDisplayed: 0.1µF  VDC_V: 50V  [0603]  (hidden comment: C0603C104K5RACAUTO)
C100  ValueDisplayed: 0.1µF  VDC_V: 50V  [0603]  (hidden comment: C0603C104K5RACAUTO)
C101  ValueDisplayed: 4.7uF  [0805_HV]  (hidden comment: GRM21BR61H475KE51L)
C102  ValueDisplayed: 4.7uF  [0805_HV]  (hidden comment: GRM21BR61H475KE51L)
C103  ValueDisplayed: 0.1µF  VDC_V: 50V  [0603]  (hidden comment: C0603C104K5RACAUTO)
C104  ValueDisplayed: 0.1µF  VDC_V: 50V  [0603]  (hidden comment: C0603C104K5RACAUTO)
C105  ValueDisplayed: 10uF  VDC_V: 35V  [1210_270]  (hidden comment: GRM32ER7YA106KA12L)
C106  ValueDisplayed: 10uF  VDC_V: 35V  [1210_270]  (hidden comment: GRM32ER7YA106KA12L)
C107  ValueDisplayed: 10uF  VDC_V: 35V  [1210_270]  (hidden comment: GRM32ER7YA106KA12L)
C108  ValueDisplayed: 0.1µF  VDC_V: 50V  [0603]  (hidden comment: C0603C104K5RACAUTO)
C109  ValueDisplayed: 0.1µF  VDC_V: 50V  [0603]  (hidden comment: C0603C104K5RACAUTO)
C110  ValueDisplayed: 10uF  VDC_V: 35V  [1210_270]  (hidden comment: GRM32ER7YA106KA12L)
C111  ValueDisplayed: 0.1µF  VDC_V: 50V  [0603]  (hidden comment: C0603C104K5RACAUTO)
C112  ValueDisplayed: 10uF  VDC_V: 35V  [1210_270]  (hidden comment: GRM32ER7YA106KA12L)
C113  ValueDisplayed: 0.1µF  VDC_V: 50V  [0603]  (hidden comment: C0603C104K5RACAUTO)
C114  ValueDisplayed: 4.7uF  [0805_HV]  (hidden comment: GRM21BR61H475KE51L)
C115  ValueDisplayed: 0.1µF  VDC_V: 50V  [0603]  (hidden comment: C0603C104K5RACAUTO)
C116  ValueDisplayed: 10uF  VDC_V: 35V  [1210_270]  (hidden comment: GRM32ER7YA106KA12L)
C119  VDC_V: 50V  ValueDisplayed: 0.47µF  [0603]  (hidden comment: GRM188R61H474KA12D)
C123  VDC_V: 100V  ValueDisplayed: 4.7µF  [1210_220]  (hidden comment: GCM32DC72A475KE02L)
C124  VDC_V: 100V  ValueDisplayed: 0.047uF  [0805_HV]  (hidden comment: GRM21BR72A473KA01L)
C125  VDC_V: 50V  ValueDisplayed: 4.7uF  [0805_HV]  (hidden comment: GRM21BR61H475KE51L)
C126  VDC_V: 20V  ValueDisplayed: 33µF  [WCAP-PSLP_630x580]  (hidden comment: 875105444004)
D9  B0520LW-7-F  value 20V  [SOD-123]
D11  B0520LW-7-F  value 20V  [SOD-123]
D18  150060VS55040  value Green  [WL-SMCD-0603]
D19  150060VS55040  value Green  [WL-SMCD-0603]
D24  B0520LW-7-F  value 20V  [SOD-123]
D25  B0520LW-7-F  value 20V  [SOD-123]
D26  150060VS55040  value Green  [WL-SMCD-0603]
D27  150060VS55040  value Green  [WL-SMCD-0603]
D28  MMSZ5232B-7-F  value 5.6V  [SOD-123]
D29  MMSZ5232B-7-F  value 5.6V  [SOD-123]
D30  B0520LW-7-F  value 20V  [SOD-123]
D31  B0520LW-7-F  value 20V  [SOD-123]
D32  150060VS55040  value Green  [WL-SMCD-0603]
D33  MMSZ5232B-7-F  value 5.6V  [SOD-123]
J27  61300211121  [WURTH_61300211121]
J29  61300211121  [WURTH_61300211121]
J30  61300211121  [WURTH_61300211121]
J33  PJ-002AH-SMT-TR  [CUI_PJ-002AH-SMT]
J34  61300211121  [WURTH_61300211121]
J39  61300211121  [WURTH_61300211121]
L11  742792662  [0603]
L12  742792662  [0603]
L15  742792662  [0603]
L16  ValueDisplayed: 22uH  [WE-PD_1210]  (hidden comment: 7447709220)
L19  74279221111  [1206]
R52  ValueDisplayed: 10.0k  [0603]  (hidden comment: ERJ-3EKF1002V)
R53  ValueDisplayed: 0  [0603]  (hidden comment: ERJ-3GEY0R00V)
R54  ValueDisplayed: 100k  [0402]  (hidden comment: CRCW0402100KFKED)
R55  ValueDisplayed: 10.0k  [0603]  (hidden comment: ERJ-3EKF1002V)
R57  ValueDisplayed: 9.09k  [0402]  (hidden comment: CRCW04029K09FKED)
R58  ValueDisplayed: 10.0k  [0603]  (hidden comment: ERJ-3EKF1002V)
R62  ValueDisplayed: 10.0k  [0603]  (hidden comment: ERJ-3EKF1002V)
R63  ValueDisplayed: 0  [0603]  (hidden comment: ERJ-3GEY0R00V)
R64  ValueDisplayed: 10.0k  [0603]  (hidden comment: ERJ-3EKF1002V)
R65  ValueDisplayed: 10.0k  [0603]  (hidden comment: ERJ-3EKF1002V)
R72  ValueDisplayed: 330  [0805_HV]  (hidden comment: CRCW0805330RJNEA)
R77  ValueDisplayed: 10.0k  [0603]  (hidden comment: ERJ-3EKF1002V)
R90  ValueDisplayed: 0  [0603]  (hidden comment: ERJ-3GEY0R00V)
R91  ValueDisplayed: 10.0k  [0603]  (hidden comment: ERJ-3EKF1002V)
R92  ValueDisplayed: 10.0k  [0603]  (hidden comment: ERJ-3EKF1002V)
R93  ValueDisplayed: 10.0k  [0603]  (hidden comment: ERJ-3EKF1002V)
R154  ValueDisplayed: 0  [0603]  (hidden comment: ERJ-3GEY0R00V)
R155  ValueDisplayed: 0  [0603]  (hidden comment: ERJ-3GEY0R00V)
R156  ValueDisplayed: 820  [0603]  (hidden comment: RC0603FR-07820RL)
R157  ValueDisplayed: 0  [0603]  (hidden comment: ERJ-3GEY0R00V)
R158  ValueDisplayed: 820  [0603]  (hidden comment: RC0603FR-07820RL)
R159  ValueDisplayed: 0  [0603]  (hidden comment: ERJ-3GEY0R00V)
R160  ValueDisplayed: 0  [0603]  (hidden comment: ERJ-3GEY0R00V)
R161  ValueDisplayed: 0  [0603]  (hidden comment: ERJ-3GEY0R00V)
R162  ValueDisplayed: 820  [0603]  (hidden comment: RC0603FR-07820RL)
R207  ValueDisplayed: 820  [0603]  (hidden comment: RC0603FR-07820RL)
R208  ValueDisplayed: 820  [0603]  (hidden comment: RC0603FR-07820RL)
T1  ValueDisplayed: 340uH  [Wurth_750313638]  (hidden comment: 750313638)
T2  ValueDisplayed: 340uH  [Wurth_750313638]  (hidden comment: 750313638)
T3  ValueDisplayed: 340uH  [Wurth_750313638]  (hidden comment: 750313638)
U2  SN6505BDBVR  [DBV0006A_L]
U7  SN6505BDBVR  [DBV0006A_L]
U10  TLV70450DBVR  [DBV0005A_N]
U11  LM76003RNPR  [RNP0030B]
U12  PTH08080WAZT  [EUG0005A]
U13  LMT87LPM  [LP0003A]
U14  LMT87LPM  [LP0003A]
U15  TLV1117LV33DCYR  [DCY0004A_N]
U16  LMT87LPM  [LP0003A]
U17  LMT87QDCKRQ1  [DCK0005A_N]
U21  TLV70450DBVR  [DBV0005A_N]
U22  SN6505BDBVR  [DBV0006A_L]
U23  TLV70450DBVR  [DBV0005A_N]

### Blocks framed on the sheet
TEMP SENSING: C39 C42 C50 C52 C53 C90-C92 J27 J29 J30 R52 R55 R58 R62 R64 R65 R77 R91-R93 U13 U14 U16 U17

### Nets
3.3V: C44.1 C49.1 C53.2 C90.2 C91.2 C92.2 R55.2 R64.2 R91.2 R208.2 U13.1(VDD) U14.1(VDD) U15.2(OUT) U15.4(OUT) U16.1(VDD) U17.1(VDD) U17.4(VDD) U17.5(VDD)
5V: C43.1 C62.1(+) C66.1 R53.2 R63.2 R159.2 R207.2 U12.3(VO) U15.3(IN)
5V_1: D28.1(K) R155.2 R156.2
5V_2: D29.1(K) R157.2 R158.2
5V_3: D33.1(K) R161.2 R162.2
24V: J33.1 J33.1A J34.2 J39.2
+6V_VDC_1: C93.1 C94.1 C97.2 C99.1 D9.1(K) D24.1(K) U10.2(IN)
+6V_VDC_2: C95.1 C96.1 C98.2 C100.1 D11.1(K) D25.1(K) U21.2(IN)
+6V_VDC_3: C110.1 C111.1 C112.2 C113.1 D30.1(K) D31.1(K) U23.2(IN)
+12V: C48.1(+) C119.1 C125.1 C126.1(+) L16.2 L19.1 R54.2 U11.9(BIAS)
+24V: C89.1(+) C123.1 C124.1 J34.1 U11.18(EN) U11.20(PVIN) U11.21(PVIN) U11.22(PVIN)
+24V_Gate_Boards: J39.1
GND: C16.1 C17.1 C26.1 C27.1 C33.1 C34.1 C38.2 C39.1 C42.1 C43.2 C44.2 C48.2(-) C49.2 C50.1 C52.1 C53.1 C61.2(-) C62.2(-) C64.2 C65.2 C66.2 C67.2 C68.2 C89.2(-) C90.1 C91.1 C92.1 C107.1 C108.1 C109.1 C119.2 C123.2 C124.2 C125.2 C126.2(-) D18.1(K) D19.1(K) J27.1 J29.1 J30.1 J33.2 J33.3 R57.1 R72.1 U2.4(GND) U2.6(CLK) U7.4(GND) U7.6(CLK) U11.7(NC) U11.13(AGND) U11.14(AGND) U11.15(AGND) U11.16(PGOOD) U11.17(SYNC/MODE) U11.19(NC) U11.23(NC) U11.24(PGND) U11.25(PGND) U11.26(PGND) U11.27(NC) U11.28(NC) U11.29(NC) U11.30(NC) U11.31(PAD) U12.2(GND) U13.3(GND) U14.3(GND) U15.1(GND) U16.3(GND) U17.2(GND) U22.4(GND) U22.6(CLK)
GND_AMC1: C65.1 C93.2 C94.2 C97.1 C99.2 C101.1 C103.2 C105.1 D26.1(K) D28.2(A) T1.5 U10.1(GND)
GND_AMC2: C67.1 C95.2 C96.2 C98.1 C100.2 C102.1 C104.2 C106.1 D27.1(K) D29.2(A) T2.5 U21.1(GND)
GND_AMC3: C68.1 C110.2 C111.2 C112.1 C113.2 C114.1 C115.2 C116.1 D32.1(K) D33.2(A) T3.5 U23.1(GND)
Temp_A: C39.2 R52.2 R58.2 ; off-sheet Temp_A
TEMP_Amb: C52.2 R93.2 ; off-sheet TEMP_Amb
Temp_B: C42.2 R62.2 R65.2 ; off-sheet Temp_B
Temp_C: C50.2 R77.2 R92.2 ; off-sheet Temp_C
NetC16_2: C16.2 C26.2 C33.2 R53.1 R90.1 T1.2 U2.2(VCC)
NetC17_2: C17.2 C27.2 C34.2 R63.1 R154.1 T2.2 U7.2(VCC)
NetC19_1: C19.1 L16.1 U11.1(SW) U11.2(SW) U11.3(SW) U11.4(SW) U11.5(SW)
NetC19_2: C19.2 U11.6(CBOOT)
NetC38_1: C38.1 U11.8(VCC)
NetC61_1: C61.1(+) C64.1 L19.2 U12.1(VI)
NetC101_2: C101.2 C103.1 L11.2 R155.1
NetC102_2: C102.2 C104.1 L12.2 R157.1
NetC105_2: C105.2 L11.1 U10.3(OUT)
NetC106_2: C106.2 L12.1 U21.3(OUT)
NetC107_2: C107.2 C108.2 C109.2 R159.1 R160.1 T3.2 U22.2(VCC)
NetC114_2: C114.2 C115.1 L15.2 R161.1
NetC116_2: C116.2 L15.1 U23.3(OUT)
NetD9_2: D9.2(A) T1.6
NetD11_2: D11.2(A) T2.6
NetD18_2: D18.2(A) R207.1
NetD19_2: D19.2(A) R208.1
NetD24_2: D24.2(A) T1.4
NetD25_2: D25.2(A) T2.4
NetD26_2: D26.2(A) R156.1
NetD27_2: D27.2(A) R158.1
NetD30_2: D30.2(A) T3.6
NetD31_2: D31.2(A) T3.4
NetD32_2: D32.2(A) R162.1
NetJ27_2: J27.2 R55.1 R58.1
NetJ29_2: J29.2 R64.1 R65.1
NetJ30_2: J30.2 R91.1 R92.1
NetR52_1: R52.1 U13.2(OUT)
NetR54_1: R54.1 R57.2 U11.12(FB)
NetR62_1: R62.1 U14.2(OUT)
NetR72_2: R72.2 U12.4(VO_ADJUST)
NetR77_1: R77.1 U16.2(OUT)
NetR90_2: R90.2 U2.5(EN)
NetR93_1: R93.1 U17.3(OUT)
NetR154_2: R154.2 U7.5(EN)
NetR160_2: R160.2 U22.5(EN)
NetT1_1: T1.1 U2.3(D2)
NetT1_3: T1.3 U2.1(D1)
NetT2_1: T2.1 U7.3(D2)
NetT2_3: T2.3 U7.1(D1)
NetT3_1: T3.1 U22.3(D2)
NetT3_3: T3.3 U22.1(D1)

Not connected (* = marked no-connect by the designer): U10 4(NC)* 5(NC)*; U11 10(RT)* 11(SS/TRK)*; U12 5(~{INHIBIT})*; U21 4(NC)* 5(NC)*; U23 4(NC)* 5(NC)*

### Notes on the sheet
- (near J27) NTC
- (near J29) NTC
- POWER SUPPLY  FOR AMC1306M05DWVR
- NON-ISOLATED POWER SUPPLY
- (near J30) NTC

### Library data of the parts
C16 C17 C93 C95 C97 C98 C105-C107 C110 C112 C116 = CMP-0009233-2: CAP, CERM, 10 uF, 35 V, +/- 10%, X7R, 1210; Manufacturer: MuRata; Polarized: N; Value: 10uF; U/M: EA; Cap_F: 10µF; Value1: Unknown; TaMin_C: -55°C; TaMax_C: 125°C; Cap_Case: 1210; AEC Category: Q200; SizeArea_mm2: 8; SizeAreaWB_mm2: 14.7; SizeX_mm: 3.2; SizeY_mm: 2.5; SizeZ_mm: 2.7
C19 = CMP-0006551-2: CAP, CERM, 0.47 uF, 6.3 V, +/- 10%, X5R, 0402; Manufacturer: MuRata; TaMin_C: -55°C; Polarized: N; SizeAreaWB_mm2: 3; Value1: Unknown; U/M: EA; Value: 0.47uF; TaMax_C: 85°C; SizeZ_mm: 0.6; SizeX_mm: 1; SizeY_mm: 0.5; Cap_F: 470nF; AEC Category: Q200
C26 C27 C33 C34 C94 C96 C99 C100 C103 C104 C108 C109 C111 C113 C115 = CMP-0079602-1: CAP, CERM, 0.1 µF, 50 V,+/- 10%, X7R, AEC-Q200 Grade 1, 0603; Manufacturer: Kemet; Polarized: N; Value: 0.1uF; U/M: EA; Cap_F: 100nF; TaMin_C: -55°C; TaMax_C: 125°C; AEC Category: Q200; AEC Grade: 1; AEC Qualified: Y; SizeArea_mm2: 1.28; SizeAreaWB_mm2: 4.68; SizeX_mm: 1.6; SizeY_mm: 0.8
C38 = CMP-0008132-2: CAP, CERM, 2.2 uF, 10 V, +/- 10%, X5R, 0805; Manufacturer: MuRata; TaMin_C: -55°C; ESR_ohm: 9m; Polarized: N; SizeAreaWB_mm2: 6.75; Value1: 0.009 ohm; U/M: EA; Value: 2.2uF; TaMax_C: 85°C; SizeZ_mm: 1.45; SizeX_mm: 2; SizeY_mm: 1.25; Cap_Case: 0805; SizeArea_mm2: 2.5; Cap_F: 2.2µF; AEC Category: Q200
C39 C42 C50 C52 C53 C90-C92 = CMP-0006979-5: CAP, CERM, 0.1 uF, 25 V, +/- 10%, X7R, 0603; Manufacturer: Kemet; Polarized: N; Value: 0.1uF; U/M: EA; Cap_F: 100nF; Value1: Unknown; TaMin_C: -55°C; TaMax_C: 125°C; AEC Category: Q200; SizeArea_mm2: 1.28; SizeAreaWB_mm2: 4.68; SizeX_mm: 1.6; SizeY_mm: 0.8; SizeZ_mm: 1
C43 C49 = CMP-0080740-1: CAP, CERM, 10 µF, 25 V,+/- 10%, X7R, 1206; Manufacturer: TDK; Polarized: N; Value: 10uF; U/M: EA; TaMin_C: -55°C; TaMax_C: 125°C; Cap_Case: 1206; SizeArea_mm2: 5.12; SizeAreaWB_mm2: 10.92; SizeX_mm: 3.2; SizeY_mm: 1.6; SizeZ_mm: 1.8; AEC Category: Q200
C44 = CMP-0006979-5: CAP, CERM, 0.1 uF, 25 V, +/- 10%, X7R, 0603; Manufacturer: Kemet; Polarized: N; Value: 0.1uF; U/M: EA; Cap_F: 100nF; Value1: Unknown; TaMin_C: -55°C; TaMax_C: 125°C; SizeArea_mm2: 1.28; SizeAreaWB_mm2: 4.68; SizeX_mm: 1.6; SizeY_mm: 0.8; SizeZ_mm: 1; AEC Category: Q200
C48 C126 = CMP-0081645-1: CAP, Aluminum Polymer, 33 µF, 20 V,+/- 20%, 0.03 ohm, D6.3xL5.8mm SMD; Manufacturer: Wurth Elektronik; IRMS_A: 2.2A; AEC Qualified: N; AEC Category: Q200; Value: 33uF; TaMax_C: 105°C; Polarized: Y; TaMin_C: -55°C; CompType: Capacitor; ESR_ohm: 0.03; Cap_Case: 6.3x5.8mm
C61 C62 = CMP-0081644-1: CAP, AL, 100 µF, 50 V, +/- 20%, SMD; Manufacturer: Wurth Elektronik; IRMS_A: 3.5dA; SizeAreaWB_mm2: 106.09; SizeArea_mm2: 68.89; AEC Qualified: N; AEC Category: Q200; Value: 100uF; TaMax_C: 105°C; SizeZ_mm: 10.5; Polarized: Y; TaMin_C: -55°C; SizeY_mm: 8.3; U/M: EA; CompType: Capacitor; Cap_Case: 8X10.5mm
C64 C66 = CMP-0079602-1: CAP, CERM, 0.1 µF, 50 V,+/- 10%, X7R, AEC-Q200 Grade 1, 0603; Manufacturer: Kemet; Polarized: N; Value: 0.1uF; U/M: EA; Cap_F: 100nF; TaMin_C: -55°C; TaMax_C: 125°C; SizeArea_mm2: 1.28; SizeAreaWB_mm2: 4.68; SizeX_mm: 1.6; SizeY_mm: 0.8; SizeZ_mm: 1; AEC Category: Q200; AEC Qualified: Y
C65 C67 C68 = CMP-0086097-1: CAP, CERM, 1000 pF, X1 760 VAC/Y1 500 VAC, +/- 20%, Y5U, 9x5mm; Manufacturer: Vishay-Bccomponents; Cap_F: 1nF; TaMin_C: -40°C; Polarized: N; VAC_Y: 500V; AEC Category: Q200; SizeY_mm: 5; SizeZ_mm: 13; U/M: EA; SizeArea_mm2: 53; VAC_X: 760V; SizeX_mm: 10.6; TaMax_C: 125°C; AC_Safety: X1Y1; SizeAreaWB_mm2: 88.2; Value: 1000pF
C89 = CMP-0081643-1: CAP, AL, 220 µF, 50 V, +/- 20%, TH; Manufacturer: Wurth Elektronik; IRMS_A: 1.385A; SizeAreaWB_mm2: 144; SizeArea_mm2: 100; AEC Qualified: N; AEC Category: Q200; Value: 220uF; TaMax_C: 105°C; SizeZ_mm: 17.5; Polarized: Y; TaMin_C: -55°C; SizeY_mm: 10; U/M: EA; CompType: Capacitor; Cap_Case: 10x16mm
C101 C102 C114 = CMP-0008309-2: CAP, CERM, 4.7 uF, 50 V, +/- 10%, X5R, 0805; Manufacturer: MuRata; Polarized: N; Value: 4.7uF; U/M: EA; Cap_F: 4.7µF; Value1: Unknown; VDC_V: 50V; TaMin_C: -55°C; TaMax_C: 85°C; Cap_Case: 0805; AEC Category: Q200; SizeArea_mm2: 2.5; SizeAreaWB_mm2: 6.75; SizeX_mm: 2; SizeY_mm: 1.25; SizeZ_mm: 1.45
C119 = CMP-0083861-1: CAP, CERM, 0.47 µF, 50 V,+/- 10%, X5R, 0603; Manufacturer: MuRata; TaMin_C: -55°C; Polarized: N; SizeAreaWB_mm2: 4.68; U/M: EA; Value: 0.47uF; TaMax_C: 85°C; SizeZ_mm: 1; SizeX_mm: 1.6; SizeY_mm: 0.8; SizeArea_mm2: 1.28; Cap_F: 470nF; AEC Category: Q200
C123 = CMP-0082268-1: CAP, CERM, 4.7 µF, 100 V,+/- 10%, X7S, AEC-Q200 Grade 1, 1210; Manufacturer: MuRata; TaMin_C: -55°C; ESR_ohm: 1m; Polarized: N; SizeAreaWB_mm2: 14.7; Value1: 0.001 ohm; U/M: EA; Value: 4.7uF; TaMax_C: 125°C; SizeZ_mm: 2.2; SizeX_mm: 3.2; SizeY_mm: 2.5; Cap_Case: 1210; SizeArea_mm2: 8; AEC Qualified: Y; IRMS_A: 6A; AEC Grade: 1; AEC Category: Q200
C124 = CMP-0008373-2: CAP, CERM, 0.047 uF, 100 V, +/- 10%, X7R, 0805; Manufacturer: MuRata; TaMin_C: -55°C; Polarized: N; SizeAreaWB_mm2: 6.75; Value1: Unknown; U/M: EA; TaMax_C: 125°C; SizeZ_mm: 1.45; SizeX_mm: 2; SizeY_mm: 1.25; Cap_Case: 0805; SizeArea_mm2: 2.5; Cap_F: 47nF; AEC Category: Q200
C125 = CMP-0008309-2: CAP, CERM, 4.7 uF, 50 V, +/- 10%, X5R, 0805; Manufacturer: MuRata; TaMin_C: -55°C; Polarized: N; SizeAreaWB_mm2: 6.75; Value1: Unknown; U/M: EA; Value: 4.7uF; TaMax_C: 85°C; SizeZ_mm: 1.45; SizeX_mm: 2; SizeY_mm: 1.25; Cap_Case: 0805; SizeArea_mm2: 2.5; Cap_F: 4.7µF; AEC Category: Q200
D9 D11 D24 D25 D30 D31 = CMP-0080707-2: Diode, Schottky, 20 V, 0.5 A, SOD-123; Manufacturer: Diodes Inc.; Vf_V: 330mV; Value1: 0.5A; Value2: 0.33V; Io_A: 500mA; TJmax_C: 125°C; AEC Category: Q101; AEC Qualified: N; SizeArea_mm2: 6.545; SizeAreaWB_mm2: 13.095; SizeX_mm: 3.85; SizeY_mm: 1.7; SizeZ_mm: 1.35
D18 D19 D26 D27 D32 = CMP-0081648-2: LED, Green, SMD; Manufacturer: Wurth Elektronik; Io_A: 20mA; Power_TotalModule: 48mW; Vr_V: 5V; SizeAreaWB_mm2: 4.68; Tjmax_C: 115°C; Value1: 0.048W; Angle: 140; SizeZ_mm: 0.5; SizeX_mm: 1.6; SizeY_mm: 0.8; Ir_A: 10µA; Vf_V: 2V; SizeArea_mm2: 1.28; Type: AlInGaP
D28 D29 D33 = CMP-0005803-3: Diode, Zener, 5.6 V, 500 mW, SOD-123; Manufacturer: Diodes Inc.; Power_W: 500mW; Value1: 0.5W; RJA_CperW: 350; AEC Category: Q101; SizeArea_mm2: 6.545; SizeAreaWB_mm2: 13.095; SizeX_mm: 3.85; SizeY_mm: 1.7; SizeZ_mm: 1.35
J27 J29 J30 J34 J39 = CMP-0054794-2: Header, 2.54 mm, 2x1, Gold, TH; Manufacturer: Wurth Elektronik; Green_Lifecycle: Active; Green_REACh: Passed; Cert_UL: Y; Gender: Male; Pitch_mm: 2.54; Row_Count: 1; Shrouded: N
J33 = CMP-0075012-1: Power Jack, SMT; Manufacturer: CUI Inc.; Green_Lifecycle: Not Set; Green_REACh: Incomplete; CNHeader: False
L11 L12 L15 = CMP-0003201-2: Ferrite Bead, 1000 ohm @ 100 MHz, 0.6 A, 0603; Manufacturer: Wurth Elektronik; Ztyp@1GHz_Ohm: 185.971; ZTyp@100MHz_Ohm: 1k; SizeAreaWB_mm2: 4.68; DCR_ohm: 3d; Value1: 0.3 ohm; Imax_A: 6dA; SizeZ_mm: 1; SizeX_mm: 1.6; SizeY_mm: 0.8; Value2: 0.6A; SizeArea_mm2: 1.28
L16 = CMP-0064538-2: Inductor, Shielded Drum Core, Ferrite, 22 uH, 5.3 A, 0.0233 ohm, SMD; Manufacturer: Wurth Elektronik; Isat: 6.5A @ 10% inductance drop; Irms: 5.3A @ 40C rise; Green_Lifecycle: Active; SizeAreaWB_mm2: 196; DCR_ohm: 0.0233; Green_REACh: Passed; Value: 22uH; Imax_A: 5.3A; SizeZ_mm: 10; SizeX_mm: 12; SizeArea_mm2: 144; Ind_H: 22µH; AEC Category: Q200
L19 = CMP-0003139-1: Ferrite Bead, 110 ohm @ 100 MHz, 5.4 A, 1206; Manufacturer: Wurth Elektronik; Ztyp@1GHz_Ohm: 43.549; ZTyp@100MHz_Ohm: 110; SizeAreaWB_mm2: 10.92; DCR_ohm: 9.5m; Value1: 0.0095 ohm; Value: 110 ohm; Imax_A: 5.4A; SizeZ_mm: 1.35; SizeX_mm: 3.2; SizeY_mm: 1.6; SizeArea_mm2: 5.12
R52 R55 R58 R62 R64 R65 R77 R91-R93 = CMP-0022684-3: RES, 10.0 k, 1%, 0.1 W, 0603; Manufacturer: Panasonic; Value: 10.0k; Res_ohm: 10k; Value_Code: 10k0; Power_W: 100mW; Value2: 0.1W; VDC_V: 75V; TempCo: 100 ppm/C; SizeArea_mm2: 1.28; SizeX_mm: 1.6; SizeY_mm: 0.8; SizeZ_mm: 1; EIA_Code: E96; U/M: EA; AEC Category: Q200
R53 R63 R90 R154 R155 R157 R159-R161 = CMP-0025874-4: RES, 0, 5%, 0.1 W, AEC-Q200 Grade 0, 0603; Manufacturer: Panasonic; Value: 0; Value_Code: 0000; Power_W: 100mW; Value2: 0.1W; VDC_V: 50V; TempCo: 600 ppm/C; EIA_Code: E24; AEC Category: Q200; AEC Qualified: Y; SizeArea_mm2: 1.28; SizeX_mm: 1.6; SizeY_mm: 0.8; SizeZ_mm: 1; SizeAreaWB_mm2: 4.68
R54 = CMP-0025950-3: RES, 100 k, 1%, 0.063 W, AEC-Q200 Grade 0, 0402; Manufacturer: Vishay-Dale; Power_W: 63mW; TempCo: 100 ppm/C; Value: 100k; EIA_Code: E96; SizeX_mm: 1; SizeY_mm: 0.5; SizeZ_mm: 0.6; Value2: 0.063W; AEC Qualified: Y; VDC_V: 50V; AEC Category: Q200; AEC Grade: 0
R57 = CMP-0026619-3: RES, 9.09 k, 1%, 0.063 W, AEC-Q200 Grade 0, 0402; Manufacturer: Vishay-Dale; Power_W: 63mW; TempCo: 100 ppm/C; Value_Code: 9k09; Value: 9.09k; EIA_Code: E96; SizeX_mm: 1; SizeY_mm: 0.5; SizeZ_mm: 0.6; Value2: 0.063W; AEC Qualified: Y; VDC_V: 50V; AEC Category: Q200; AEC Grade: 0
R72 = CMP-0020527-3: RES, 330, 5%, 0.125 W, AEC-Q200 Grade 0, 0805; Manufacturer: Vishay-Dale; Value: 330; Value_Code: 330R; Power_W: 125mW; Value2: 0.125W; VDC_V: 150V; TempCo: 200 ppm/C; SizeArea_mm2: 2.5; SizeX_mm: 2; SizeY_mm: 1.25; SizeZ_mm: 1.45; EIA_Code: E24; AEC Category: Q200; AEC Qualified: Y; AEC Grade: 0
R156 R158 R162 R207 R208 = CMP-0023288-5: RES, 820, 1%, 0.1 W, 0603; Manufacturer: Yageo; Value: 820; Value_Code: 820R; Power_W: 100mW; Value2: 0.1W; VDC_V: 75V; TempCo: 100 ppm/C; SizeArea_mm2: 1.28; SizeX_mm: 1.6; SizeY_mm: 0.8; SizeZ_mm: 1; AEC Category: Q200; AEC Qualified: N; SizeAreaWB_mm2: 4.68
T1-T3 = CMP-0030601-1: Transformer, 340 uH, SMT; Manufacturer: Wurth Elektronik; Value: 340uH; Lp: 340; DCR_ohm: 3.3d; Ind_H: 340µH
U2 U7 U22 = CMP-0076095-1: Low-Noise 1 A, 420 kHz Transformer Driver, DBV0006A (SOT-23-6); Alternate PartNumber: SN6505BDBVT; Manufacturer: Texas Instruments; CompType: IC; U/M: EA; Green_Lifecycle: Active; Green_REACh: Passed; SizeArea_mm2: 8.12; SizeAreaWB_mm2: 14.82; SizeX_mm: 2.8; SizeY_mm: 2.9; SizeZ_mm: 1.45
U10 U21 U23 = CMP-0035558-1: Single Output LDO, 150 mA, Fixed 5 V Output, 2.5 to 24 V Input, with Ultra-Low IQ, 5-pin SOT-23 (DBV), -40 to 125 degC, Green (RoHS & no Sb/Br); Manufacturer: Texas Instruments; Accuracy(%): 2; Fixed Output Options(V): 5; Iout(Max)(A): 0.15; Iq(Typ)(mA): 0.003; SubFamily: Single Channel LDO; Vdo(Typ)(mV): 400; Vin(Max)(V): 24; Vin(Min)(V): 2.5
U11 = CMP-0013938-2: SIMPLE SWITCHER 3.5V to 60V 3.5A Synchronous Step-Down Voltage Regulator, RNP0030B (WQFN-30); Manufacturer: Texas Instruments; Alternate PartNumber: LM76003RNPT; SizeX_mm: 4; SizeY_mm: 6; CompType: IC; SizeZ_mm: 0.8; SizeArea_mm2: 24; SizeAreaWB_mm2: 48; U/M: EA
U12 = CMP-0031048-1: 2.25 A, 4.5 to 18 V Input Wide Adjust Miniature Power Module, -40 to 85 degC, 5-pin Module (EUG5), Pb-Free (RoHS); Manufacturer: Texas Instruments; Iout(Max)(A): 2.25; Regulated Outputs(#): 1; SubFamily: Non-Isolated POL; Vin(Max)(V): 18; Vin(Min)(V): 4.5; VO Adjustable: TRUE; Vout(Max)(V): 5.5; Vout(Min)(V): 0.9
U13 U14 U16 = CMP-0076507-3: 2.7V-Capable, 10 uA Analog Output Temperature Sensor in SC70 and TO-92, LP0003A (TO-92-3); Manufacturer: Texas Instruments; SizeArea_mm2: 18.4; SizeAreaWB_mm2: 39.76; SizeX_mm: 3.68; SizeY_mm: 5.0; SizeZ_mm: 9.33; CompType: IC; AEC Category: Q200; AEC Qualified: N; Rating: Catalog
U15 = CMP-0036760-1: Single Output LDO, 1 A, Fixed 3.3 V Output, 2 to 5.5 V Input, 4-pin SOT-223 (DCY), -40 to 125 degC, Green (RoHS & no Sb/Br); Manufacturer: Texas Instruments; Accuracy(%): 2; Fixed Output Options(V): 3.3; Iout(Max)(A): 1; Iq(Typ)(mA): 0.05; SubFamily: Single Channel LDO; Vdo(Typ)(mV): 1200; Vin(Max)(V): 5.5
U17 = CMP-0066236-2: Automotive Grade, 2.7V-Capable, 10 uA Analog Output Temperature Sensor, DCK0005A (SOT-SC70-5); Alternate PartNumber: LMT87QDCKTQ1; Manufacturer: Texas Instruments; SizeArea_mm2: 4.2; SizeAreaWB_mm2: 9.3; SizeX_mm: 2.1; SizeY_mm: 2.0; SizeZ_mm: 1.1; CompType: IC; AEC Category: Q200; AEC Qualified: Y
